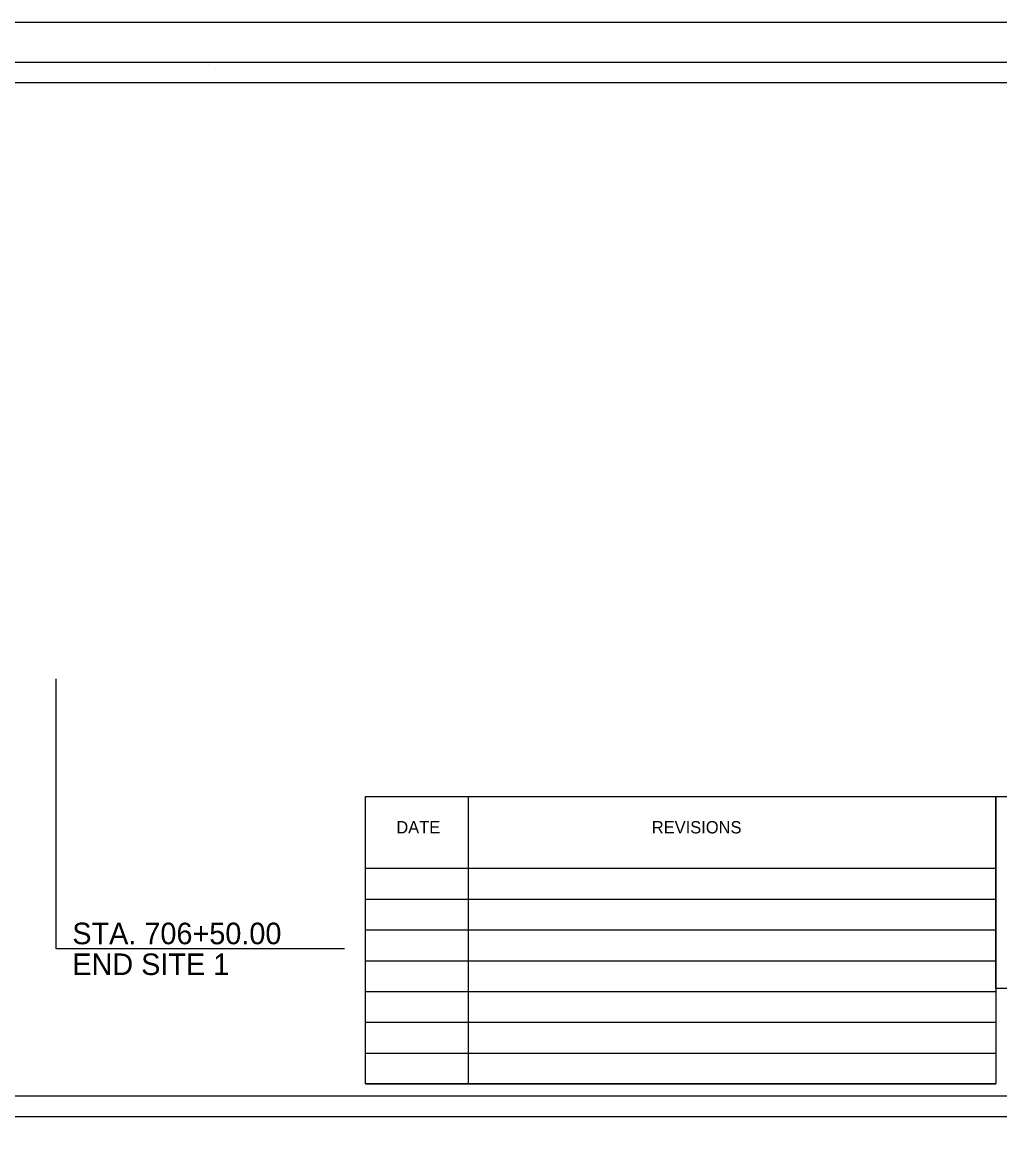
# Model space of a CAD drawing. Extents: x 814841 to 962585, y -174183 to 1802800.
# Drawn here: x 815574 to 816051, y 1802262 to 1802800 of the extents above; entities that cross this region are included whole.
import ezdxf

# ---------------------------------------------------------------- set-up
doc = ezdxf.new("R2010")
doc.units = 0
for name, color, linetype in [('Legend', 7, 'Continuous'), ('R_Border', 7, 'Continuous'), ('R_Border Notes', 7, 'Continuous'), ('R_Border Plan-Plan', 7, 'Continuous'), ('R_Detour Annot', 7, 'Continuous'), ('R_Draft', 7, 'Continuous'), ('R_No Plot', 7, 'Continuous')]:
    doc.layers.add(name, color=color, linetype=linetype)

msp = doc.modelspace()

# ---------------------------------------------------------------- linework, layer by layer
at = {"layer": 'Legend'}
msp.add_lwpolyline([(816048.79, 1802422.91), (816213.79, 1802422.91), (816213.79, 1802329.38), (816048.79, 1802329.38)], close=True, dxfattribs=at)
at = {"layer": 'R_Border'}
for p, q in [((814902.59, 1802780.6), (816483.49, 1802780.6)), ((815665.19, 1802779.3), (815665.19, 1802779.3)), ((815665.19, 1802779.3), (815665.19, 1802779.3))]:
    msp.add_line(p, q, dxfattribs=at)
at = {"layer": 'R_Border Notes'}
for p, q in [((815791.77, 1802422.91), (816048.79, 1802422.91)), ((815791.77, 1802422.91), (815791.77, 1802282.91)), ((815741.77, 1802387.91), (816048.79, 1802387.91)), ((815741.77, 1802372.91), (816048.79, 1802372.91)), ((815741.77, 1802357.91), (816048.79, 1802357.91)), ((815741.77, 1802342.91), (816048.79, 1802342.91)), ((815741.77, 1802327.91), (816048.79, 1802327.91)), ((815741.77, 1802312.91), (816048.79, 1802312.91)), ((815741.77, 1802297.91), (816048.79, 1802297.91)), ((815741.77, 1802282.91), (816048.79, 1802282.91))]:
    msp.add_line(p, q, dxfattribs=at)
msp.add_lwpolyline([(815741.77, 1802422.91), (816048.79, 1802422.91), (816048.79, 1802282.91), (815741.77, 1802282.91)], close=True, dxfattribs=at)
at = {"layer": 'R_Border Plan-Plan'}
msp.add_line((814902.59, 1802266.95), (816483.49, 1802266.95), dxfattribs=at)
at = {"layer": 'R_Draft'}
for p, q in [((815591.14, 1802348.68), (815591.14, 1802480.12)), ((815731.54, 1802348.68), (815591.14, 1802348.68))]:
    msp.add_line(p, q, dxfattribs=at)
at = {"layer": 'R_No Plot'}
for points in [[(814840.55, 1802800.08), (816507.25, 1802800.08), (816507.25, 1801733.39), (814840.55, 1801733.39)], [(816473.49, 1802276.95), (814912.59, 1802276.95), (814912.59, 1802770.6), (816160.29, 1802770.6), (816160.29, 1802721.2), (816247.99, 1802721.2), (816368.49, 1802721.2), (816368.49, 1802609.54), (816473.49, 1802609.54)], [(814912.59, 1802770.6), (816160.29, 1802770.6), (816160.29, 1802721.2), (816247.99, 1802721.2), (816368.49, 1802721.2), (816368.49, 1802609.54), (816473.49, 1802609.54), (816473.49, 1801763.3), (814912.59, 1801763.3)], [(816473.49, 1802276.95), (814912.59, 1802276.95), (814912.59, 1802770.6), (816160.29, 1802770.6), (816160.29, 1802721.2), (816247.99, 1802721.2), (816368.49, 1802721.2), (816368.49, 1802609.54), (816473.49, 1802609.54)]]:
    msp.add_lwpolyline(points, close=True, dxfattribs=at)

# ---------------------------------------------------------------- texts
at = {"layer": 'Legend'}
for s, p in [('DATE', (815756.77, 1802404.91)), ('  REVISIONS', (815876.77, 1802404.91))]:
    msp.add_text(s, height=6, dxfattribs=at).set_placement(p)
at = {"layer": 'R_Detour Annot'}
for s, p in [('STA. 706+50.00', (815598.93, 1802350.93)), ('END SITE 1', (815598.93, 1802335.93))]:
    msp.add_text(s, height=10.5, dxfattribs=at).set_placement(p)

doc.saveas('drawing.dxf')
